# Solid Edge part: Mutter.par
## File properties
Sűrűség: 0,000 kg/m^3
Pontosság: 0,990
Author: ahadarics
Last saved by: psaghy
Revision: 77
Username: ahadarics
Dokumentum tartalom típus: 0
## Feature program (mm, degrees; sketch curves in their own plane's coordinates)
base feature "unnamed BaseFeature 1"
sketch for "Furat_1" plane through (6, 0, 0) normal (1, 0, 0) x-axis (0, -1, 0)
  hole centre (0, 0) bore radius 4.3235
hole "Furat_1" through  StartChamferOffset = 0.39 mm; StartChamferAngle = 45 deg
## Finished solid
Body 1: solid body, 23 faces, 47 edges, 26 vertices.
  Faces by surface: cone 14, plane 8, cylinder 1
  Edges by curve: spline 24, circle 16, line 7
Bounding box of the edges (mm): 6.000 x 19.630 x 17.000, from (0, -9.815, -8.5) to (6, 9.815, 8.5).
Cylindrical faces by radius (mm): R4.3235 x1
Conical faces (half-angle, radius in mm at the cone's reference point): 45 deg R4.7135 x1, 60 deg R4.6618 x1, 60 deg R9.1575 x12
Planar faces by outward normal: +x 1, +z 1, -x 1, -z 1, oblique 4
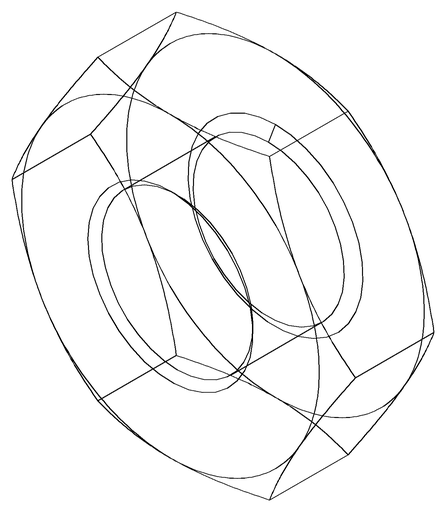
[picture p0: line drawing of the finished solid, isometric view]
